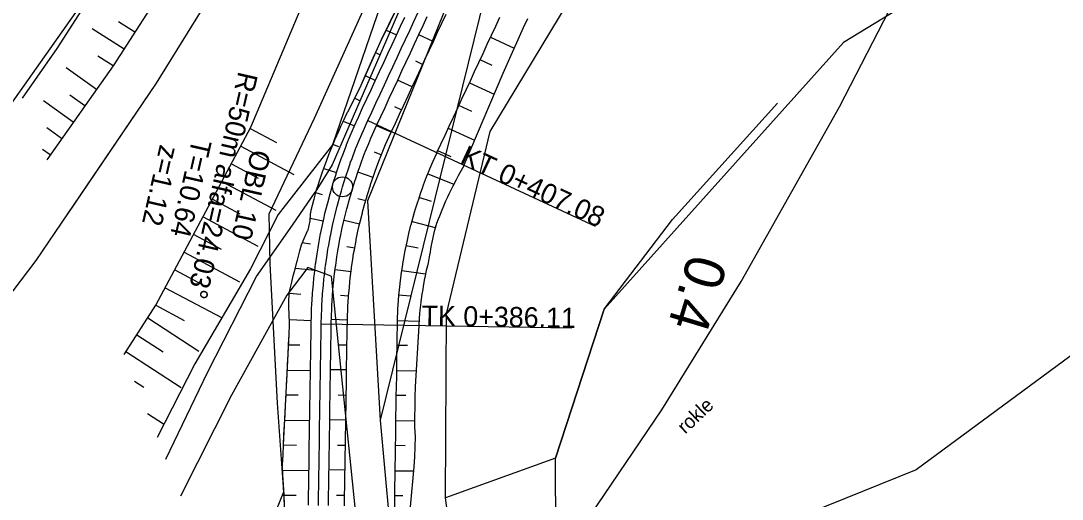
# Model space of a CAD drawing. Extents: x -583721 to -583071, y -1166145 to -1165065.
# Drawn here: x -583498.8 to -583394.9, y -1165295.2 to -1165247.5 of the extents above; entities that cross this region are included whole.
import ezdxf

# ---------------------------------------------------------------- set-up
doc = ezdxf.new("R2010")
doc.units = 0
for name, color, linetype in [('01_DOPRAVA', 7, 'Continuous'), ('03_PC_POPIS_NAVRH', 7, 'Continuous'), ('14', 7, 'Continuous'), ('21', 7, 'Continuous'), ('28', 7, 'Continuous'), ('_Rozpiska', 7, 'Continuous'), ('Kabel_navrh', 7, 'Continuous'), ('KOTY', 7, 'Continuous'), ('Popis PP', 7, 'Continuous'), ('Rámy', 7, 'Continuous'), ('TISK', 7, 'Continuous'), ('Trojúhelniky', 7, 'Continuous')]:
    doc.layers.add(name, color=color, linetype=linetype)

msp = doc.modelspace()

# ---------------------------------------------------------------- linework, layer by layer
at = {"layer": '01_DOPRAVA'}
for points in [[(-583322.15, -1165168.47), (-583340.5, -1165179.46), (-583360.81, -1165200.75), (-583377.25, -1165221.89), (-583390.68, -1165233.74), (-583416.76, -1165249.61), (-583440.61, -1165276.22), (-583445.47, -1165291.1), (-583456.44, -1165295.04)], [(-583479.19, -1165311.26), (-583476.42, -1165303.92), (-583472.55, -1165294.46), (-583473.2, -1165285.59), (-583473.93, -1165271.71), (-583474.02, -1165266.7), (-583469.49, -1165257.18), (-583464.2, -1165245.36), (-583457.16, -1165229.52), (-583453.53, -1165221.51), (-583450.9, -1165215.7), (-583447.13, -1165205.68)], [(-583456.44, -1165295.04), (-583456.33, -1165276.69), (-583451.99, -1165258.51), (-583437.4, -1165234.32), (-583437.26, -1165214.82), (-583447.13, -1165205.68)], [(-583472.25, -1165207.93), (-583489.98, -1165241.85), (-583516.01, -1165278.67)], [(-583327.43, -1165211.57), (-583337.15, -1165221.16), (-583345.28, -1165232.38), (-583356.63, -1165240.96), (-583373.5, -1165261.36), (-583381.99, -1165269.78), (-583390.9, -1165278.52), (-583409.51, -1165292.26), (-583429.18, -1165300.2), (-583454.83, -1165307.19)], [(-583454.83, -1165307.19), (-583455.42, -1165302.7), (-583456.44, -1165295.04)]]:
    msp.add_lwpolyline(points, dxfattribs=at)
at = {"layer": '03_PC_POPIS_NAVRH'}
for points in [[(-583461.6, -1165204.29), (-583455.65, -1165207.26), (-583450.35, -1165210.72), (-583447.26, -1165215.15), (-583446.51, -1165221.03), (-583447.68, -1165226.67), (-583452.2, -1165235.68), (-583464.21, -1165265.43), (-583462.94, -1165287.3)], [(-583463.26, -1165207.24), (-583457.44, -1165210.02), (-583453.98, -1165212.63), (-583451.69, -1165216.62), (-583450.94, -1165221.07), (-583451.57, -1165225.85), (-583455.47, -1165233.56), (-583467.74, -1165261.81), (-583469.44, -1165264.56)], [(-583484.34, -1165291.2), (-583480.19, -1165282.54), (-583475.3, -1165272.95), (-583471.69, -1165267.86), (-583469.44, -1165264.56)], [(-583467.84, -1165272.94), (-583470.17, -1165272.08), (-583472.25, -1165274.84), (-583477.78, -1165284.8), (-583482.88, -1165294.88)], [(-583467.84, -1165272.94), (-583464.75, -1165303.13)], [(-583462.94, -1165287.3), (-583461.59, -1165302.25)]]:
    msp.add_lwpolyline(points, dxfattribs=at)
at = {"layer": '14'}
for p, q in [((-583462.35, -1165248.38), (-583461.32, -1165248.86)), ((-583457.66, -1165249.53), (-583459.11, -1165248.85)), ((-583451.95, -1165249.09), (-583449.59, -1165250.19)), ((-583462.9, -1165250.89), (-583463.42, -1165250.64)), ((-583459.44, -1165251.46), (-583458.71, -1165251.8)), ((-583451.8, -1165251.92), (-583453, -1165251.36)), ((-583464.44, -1165252.93), (-583463.43, -1165253.4)), ((-583459.77, -1165254.06), (-583461.22, -1165253.39)), ((-583454.05, -1165253.63), (-583451.59, -1165254.77)), ((-583464.99, -1165255.43), (-583465.5, -1165255.19)), ((-583461.54, -1165255.99), (-583460.82, -1165256.33)), ((-583453.83, -1165256.49), (-583455.1, -1165255.9)), ((-583466.63, -1165257.46), (-583465.52, -1165257.94)), ((-583461.86, -1165258.58), (-583463.32, -1165257.92)), ((-583456.16, -1165258.16), (-583453.54, -1165259.38)), ((-583467.07, -1165260.02), (-583467.66, -1165259.79)), ((-583463.57, -1165260.52), (-583462.83, -1165260.82)), ((-583455.86, -1165261.04), (-583457.21, -1165260.43)), ((-583468.59, -1165262.18), (-583467.31, -1165262.6)), ((-583463.67, -1165263.08), (-583465.18, -1165262.56)), ((-583458.21, -1165262.72), (-583455.62, -1165263.76)), ((-583468.7, -1165264.81), (-583469.37, -1165264.63)), ((-583465.17, -1165265.17), (-583464.4, -1165265.39)), ((-583457.84, -1165265.48), (-583459.06, -1165265.07)), ((-583469.93, -1165267.14), (-583468.63, -1165267.42)), ((-583465.01, -1165267.73), (-583466.56, -1165267.37)), ((-583459.78, -1165267.47), (-583457.46, -1165268.09)), ((-583469.91, -1165269.74), (-583470.72, -1165269.6)), ((-583466.28, -1165269.96), (-583465.49, -1165270.1)), ((-583459.16, -1165270.15), (-583460.36, -1165269.9)), ((-583471.41, -1165272.12), (-583469.47, -1165272.35)), ((-583465.86, -1165272.49), (-583467.45, -1165272.29)), ((-583460.8, -1165272.36), (-583458.43, -1165272.7)), ((-583470.86, -1165274.76), (-583472.02, -1165274.67)), ((-583466.9, -1165274.83), (-583466.1, -1165274.89)), ((-583459.96, -1165274.94), (-583461.08, -1165274.84)), ((-583472.01, -1165277.27), (-583469.83, -1165277.34)), ((-583466.22, -1165277.32), (-583467.82, -1165277.27)), ((-583461.22, -1165277.34), (-583459.08, -1165277.42)), ((-583470.98, -1165279.82), (-583472.09, -1165279.8)), ((-583467.07, -1165279.78), (-583466.27, -1165279.79)), ((-583460.24, -1165279.85), (-583461.27, -1165279.84)), ((-583472.22, -1165282.3), (-583469.91, -1165282.34)), ((-583466.31, -1165282.29), (-583467.9, -1165282.27)), ((-583461.31, -1165282.34), (-583459.36, -1165282.37)), ((-583471.14, -1165284.82), (-583472.34, -1165284.8)), ((-583467.14, -1165284.78), (-583466.34, -1165284.79)), ((-583460.41, -1165284.85), (-583461.34, -1165284.84)), ((-583472.47, -1165287.3), (-583469.98, -1165287.34)), ((-583466.38, -1165287.29), (-583467.98, -1165287.27)), ((-583461.38, -1165287.34), (-583459.52, -1165287.37)), ((-583471.31, -1165289.81), (-583472.6, -1165289.8)), ((-583467.22, -1165289.78), (-583466.42, -1165289.79)), ((-583460.46, -1165289.85), (-583461.42, -1165289.84)), ((-583472.67, -1165292.29), (-583470.06, -1165292.33)), ((-583466.46, -1165292.29), (-583468.06, -1165292.27)), ((-583461.46, -1165292.34), (-583459.65, -1165292.36)), ((-583471.32, -1165294.82), (-583472.54, -1165294.8)), ((-583467.3, -1165294.78), (-583466.5, -1165294.79)), ((-583460.69, -1165294.85), (-583461.5, -1165294.84))]:
    msp.add_line(p, q, dxfattribs=at)
at = {"layer": '21'}
for points in [[(-583472.33, -1165298.76), (-583472.65, -1165292.75), (-583472.69, -1165291.75), (-583472.64, -1165290.75), (-583472.6, -1165289.75), (-583472.04, -1165278.76), (-583471.99, -1165277.76), (-583471.99, -1165277.65), (-583472.04, -1165276.7), (-583472.06, -1165276.06), (-583472.06, -1165275.64), (-583472.02, -1165274.57), (-583471.99, -1165274.46), (-583471.77, -1165273.52), (-583471.62, -1165272.9), (-583471.51, -1165272.48), (-583471.22, -1165271.45), (-583471.19, -1165271.35), (-583470.98, -1165270.42), (-583470.81, -1165269.81), (-583470.63, -1165269.41), (-583470.19, -1165268.42), (-583470.15, -1165268.33), (-583469.93, -1165267.41), (-583469.92, -1165266.78), (-583469.83, -1165266.36), (-583469.57, -1165265.34), (-583469.55, -1165265.25), (-583469.29, -1165264.33), (-583469.11, -1165263.75), (-583468.98, -1165263.33), (-583468.65, -1165262.34), (-583468.62, -1165262.26), (-583468.29, -1165261.36), (-583468.07, -1165260.79), (-583467.91, -1165260.38), (-583467.51, -1165259.42), (-583467.47, -1165259.34), (-583467.09, -1165258.46), (-583466.84, -1165257.91), (-583466.66, -1165257.51), (-583466.2, -1165256.57), (-583466.16, -1165256.5), (-583465.29, -1165254.78), (-583464.86, -1165253.88), (-583463.23, -1165250.22), (-583462.81, -1165249.32), (-583458.45, -1165240.32)], [(-583472.49, -1165295.76), (-583472.54, -1165294.76), (-583472.6, -1165293.76), (-583472.65, -1165292.75), (-583472.69, -1165291.75), (-583472.64, -1165290.75), (-583472.6, -1165289.75), (-583472.55, -1165288.76), (-583472.5, -1165287.76), (-583472.44, -1165286.76), (-583472.39, -1165285.76), (-583472.34, -1165284.76), (-583472.29, -1165283.76), (-583472.24, -1165282.76), (-583472.19, -1165281.76), (-583472.14, -1165280.76), (-583472.09, -1165279.76), (-583472.04, -1165278.76), (-583471.99, -1165277.76), (-583471.99, -1165277.65), (-583472.04, -1165276.7), (-583472.06, -1165276.06), (-583472.06, -1165275.64), (-583472.02, -1165274.57), (-583471.99, -1165274.46), (-583471.77, -1165273.52), (-583471.62, -1165272.9), (-583471.51, -1165272.48), (-583471.22, -1165271.45), (-583471.19, -1165271.35), (-583470.98, -1165270.42), (-583470.81, -1165269.81), (-583470.63, -1165269.41), (-583470.19, -1165268.42), (-583470.15, -1165268.33), (-583469.93, -1165267.41), (-583469.92, -1165266.78), (-583469.83, -1165266.36), (-583469.57, -1165265.34), (-583469.55, -1165265.25), (-583469.29, -1165264.33), (-583469.11, -1165263.75), (-583468.98, -1165263.33), (-583468.65, -1165262.34), (-583468.62, -1165262.26), (-583468.29, -1165261.36), (-583468.07, -1165260.79), (-583467.91, -1165260.38), (-583467.51, -1165259.42), (-583467.47, -1165259.34), (-583467.09, -1165258.46), (-583466.84, -1165257.91), (-583466.66, -1165257.51), (-583466.2, -1165256.57), (-583466.16, -1165256.5), (-583465.74, -1165255.67), (-583465.29, -1165254.78), (-583464.86, -1165253.88), (-583464.45, -1165252.96), (-583464.05, -1165252.05), (-583463.64, -1165251.14), (-583463.23, -1165250.22), (-583462.81, -1165249.32), (-583462.37, -1165248.42), (-583461.93, -1165247.52), (-583461.5, -1165246.62)], [(-583470.11, -1165295.79), (-583470.1, -1165294.79), (-583470.08, -1165293.79), (-583470.07, -1165292.79), (-583470.05, -1165291.79), (-583470.04, -1165290.79), (-583470.02, -1165289.79), (-583470.01, -1165288.79), (-583469.99, -1165287.79), (-583469.97, -1165286.8), (-583469.96, -1165285.8), (-583469.94, -1165284.8), (-583469.93, -1165283.8), (-583469.91, -1165282.8), (-583469.9, -1165281.8), (-583469.88, -1165280.8), (-583469.87, -1165279.8), (-583469.85, -1165278.8), (-583469.84, -1165277.8), (-583469.83, -1165277.69), (-583469.81, -1165276.78), (-583469.79, -1165276.16), (-583469.77, -1165275.76), (-583469.7, -1165274.74), (-583469.7, -1165274.64), (-583469.62, -1165273.73), (-583469.56, -1165273.11), (-583469.51, -1165272.71), (-583469.39, -1165271.7), (-583469.37, -1165271.6), (-583469.24, -1165270.69), (-583469.15, -1165270.09), (-583469.08, -1165269.68), (-583468.89, -1165268.68), (-583468.87, -1165268.58), (-583468.69, -1165267.68), (-583468.55, -1165267.09), (-583468.46, -1165266.69), (-583468.21, -1165265.7), (-583468.19, -1165265.61), (-583467.95, -1165264.71), (-583467.78, -1165264.13), (-583467.66, -1165263.73), (-583467.36, -1165262.76), (-583467.33, -1165262.68), (-583467.03, -1165261.79), (-583466.84, -1165261.23), (-583466.69, -1165260.83), (-583466.33, -1165259.88), (-583466.3, -1165259.8), (-583465.95, -1165258.93), (-583465.72, -1165258.39), (-583465.55, -1165257.99), (-583465.13, -1165257.06), (-583465.1, -1165256.99), (-583464.71, -1165256.15), (-583464.29, -1165255.25), (-583463.86, -1165254.34), (-583463.44, -1165253.43), (-583463.02, -1165252.53), (-583462.6, -1165251.62), (-583462.18, -1165250.71), (-583461.76, -1165249.81), (-583461.34, -1165248.9), (-583460.92, -1165247.99), (-583460.49, -1165247.09)], [(-583468.11, -1165295.82), (-583468.1, -1165294.82), (-583468.08, -1165293.83), (-583468.07, -1165292.83), (-583468.05, -1165291.83), (-583468.04, -1165290.83), (-583468.02, -1165289.83), (-583468.01, -1165288.83), (-583467.99, -1165287.83), (-583467.98, -1165286.83), (-583467.96, -1165285.83), (-583467.94, -1165284.83), (-583467.93, -1165283.83), (-583467.91, -1165282.83), (-583467.9, -1165281.83), (-583467.88, -1165280.83), (-583467.87, -1165279.83), (-583467.85, -1165278.83), (-583467.84, -1165277.83), (-583467.83, -1165277.72), (-583467.81, -1165276.85), (-583467.79, -1165276.25), (-583467.77, -1165275.87), (-583467.71, -1165274.89), (-583467.7, -1165274.79), (-583467.63, -1165273.91), (-583467.57, -1165273.33), (-583467.53, -1165272.94), (-583467.41, -1165271.96), (-583467.39, -1165271.87), (-583467.27, -1165270.99), (-583467.17, -1165270.42), (-583467.11, -1165270.03), (-583466.93, -1165269.06), (-583466.91, -1165268.97), (-583466.73, -1165268.1), (-583466.6, -1165267.54), (-583466.51, -1165267.15), (-583466.28, -1165266.2), (-583466.26, -1165266.11), (-583466.02, -1165265.25), (-583465.86, -1165264.7), (-583465.75, -1165264.31), (-583465.46, -1165263.37), (-583465.43, -1165263.29), (-583465.14, -1165262.45), (-583464.95, -1165261.91), (-583464.81, -1165261.52), (-583464.47, -1165260.61), (-583464.44, -1165260.53), (-583464.1, -1165259.7), (-583463.88, -1165259.17), (-583463.72, -1165258.8), (-583463.31, -1165257.9), (-583463.28, -1165257.83), (-583462.89, -1165257), (-583462.47, -1165256.09), (-583462.05, -1165255.18), (-583461.63, -1165254.28), (-583461.21, -1165253.37), (-583460.79, -1165252.46), (-583460.37, -1165251.56), (-583459.94, -1165250.65), (-583459.52, -1165249.74), (-583459.1, -1165248.83), (-583458.68, -1165247.93), (-583458.26, -1165247.02)], [(-583466.51, -1165295.85), (-583466.5, -1165294.85), (-583466.48, -1165293.85), (-583466.47, -1165292.85), (-583466.45, -1165291.85), (-583466.44, -1165290.85), (-583466.42, -1165289.85), (-583466.41, -1165288.85), (-583466.39, -1165287.85), (-583466.38, -1165286.85), (-583466.36, -1165285.85), (-583466.34, -1165284.85), (-583466.33, -1165283.85), (-583466.31, -1165282.85), (-583466.3, -1165281.85), (-583466.28, -1165280.85), (-583466.27, -1165279.85), (-583466.25, -1165278.85), (-583466.24, -1165277.85), (-583466.23, -1165277.74), (-583466.21, -1165276.9), (-583466.19, -1165276.32), (-583466.17, -1165275.95), (-583466.11, -1165275.01), (-583466.11, -1165274.91), (-583466.03, -1165274.06), (-583465.98, -1165273.49), (-583465.94, -1165273.12), (-583465.82, -1165272.18), (-583465.81, -1165272.08), (-583465.68, -1165271.24), (-583465.6, -1165270.68), (-583465.53, -1165270.3), (-583465.36, -1165269.37), (-583465.34, -1165269.28), (-583465.17, -1165268.44), (-583465.04, -1165267.89), (-583464.96, -1165267.52), (-583464.73, -1165266.6), (-583464.71, -1165266.52), (-583464.48, -1165265.68), (-583464.33, -1165265.15), (-583464.22, -1165264.77), (-583463.93, -1165263.87), (-583463.91, -1165263.79), (-583463.63, -1165262.97), (-583463.45, -1165262.45), (-583463.31, -1165262.08), (-583462.98, -1165261.19), (-583462.95, -1165261.12), (-583462.62, -1165260.31), (-583462.41, -1165259.81), (-583462.25, -1165259.44), (-583461.86, -1165258.57), (-583461.83, -1165258.51), (-583461.44, -1165257.67), (-583461.02, -1165256.76), (-583460.6, -1165255.86), (-583460.18, -1165254.95), (-583459.76, -1165254.04), (-583459.34, -1165253.14), (-583458.91, -1165252.23), (-583458.49, -1165251.32), (-583458.07, -1165250.42), (-583457.65, -1165249.51), (-583457.23, -1165248.6), (-583456.81, -1165247.69), (-583456.39, -1165246.79)], [(-583461.51, -1165295.93), (-583461.5, -1165294.93), (-583461.48, -1165293.93), (-583461.47, -1165292.93), (-583461.45, -1165291.93), (-583461.44, -1165290.93), (-583461.42, -1165289.93), (-583461.41, -1165288.93), (-583461.39, -1165287.93), (-583461.38, -1165286.93), (-583461.36, -1165285.93), (-583461.35, -1165284.93), (-583461.33, -1165283.93), (-583461.31, -1165282.93), (-583461.3, -1165281.93), (-583461.28, -1165280.93), (-583461.27, -1165279.93), (-583461.25, -1165278.93), (-583461.24, -1165277.93), (-583461.24, -1165277.82), (-583461.22, -1165277.06), (-583461.2, -1165276.55), (-583461.18, -1165276.22), (-583461.13, -1165275.37), (-583461.12, -1165275.28), (-583461.06, -1165274.53), (-583461.01, -1165274.02), (-583460.97, -1165273.68), (-583460.86, -1165272.84), (-583460.85, -1165272.76), (-583460.74, -1165272), (-583460.66, -1165271.5), (-583460.61, -1165271.16), (-583460.45, -1165270.33), (-583460.44, -1165270.25), (-583460.28, -1165269.5), (-583460.17, -1165269.01), (-583460.09, -1165268.67), (-583459.89, -1165267.85), (-583459.87, -1165267.78), (-583459.67, -1165267.03), (-583459.53, -1165266.55), (-583459.43, -1165266.22), (-583459.18, -1165265.41), (-583459.15, -1165265.34), (-583458.91, -1165264.6), (-583458.74, -1165264.14), (-583458.62, -1165263.81), (-583458.32, -1165263.01), (-583458.3, -1165262.95), (-583458, -1165262.23), (-583457.81, -1165261.77), (-583457.67, -1165261.45), (-583457.32, -1165260.67), (-583457.3, -1165260.61), (-583456.91, -1165259.78), (-583456.49, -1165258.87), (-583456.06, -1165257.96), (-583455.64, -1165257.06), (-583455.22, -1165256.15), (-583454.8, -1165255.24), (-583454.38, -1165254.34), (-583453.96, -1165253.43), (-583453.54, -1165252.52), (-583453.12, -1165251.61), (-583452.69, -1165250.71), (-583452.27, -1165249.8), (-583451.85, -1165248.89), (-583451.43, -1165247.99), (-583451.01, -1165247.08)], [(-583448.26, -1165247.26), (-583448.69, -1165248.16), (-583450.32, -1165251.81), (-583450.72, -1165252.73), (-583454.6, -1165261.87), (-583454.62, -1165261.92), (-583455.01, -1165262.62), (-583455.17, -1165262.91), (-583455.39, -1165263.31), (-583455.72, -1165263.96), (-583455.75, -1165264.02), (-583456.1, -1165264.74), (-583456.24, -1165265.04), (-583456.43, -1165265.46), (-583456.72, -1165266.13), (-583456.75, -1165266.19), (-583457.05, -1165266.94), (-583457.17, -1165267.24), (-583457.34, -1165267.69), (-583457.55, -1165268.38), (-583457.56, -1165268.45), (-583457.74, -1165269.23), (-583457.8, -1165269.55), (-583457.89, -1165270.02), (-583458.02, -1165270.73), (-583458.03, -1165270.8), (-583458.18, -1165271.59), (-583458.25, -1165271.9), (-583458.36, -1165272.37), (-583458.5, -1165273.08), (-583458.52, -1165273.16), (-583458.66, -1165273.94), (-583458.71, -1165274.26), (-583458.79, -1165274.74), (-583458.89, -1165275.45), (-583458.9, -1165275.53), (-583458.99, -1165276.33), (-583459.02, -1165276.65), (-583459.06, -1165277.14), (-583459.11, -1165277.85), (-583459.45, -1165283.96), (-583459.49, -1165284.96), (-583459.52, -1165287.96), (-583459.48, -1165288.96), (-583459.5, -1165289.96), (-583459.53, -1165290.96), (-583459.61, -1165291.96), (-583459.98, -1165295.95)]]:
    msp.add_lwpolyline(points, dxfattribs=at)
at = {"layer": '_Rozpiska'}
for points in [[(-583487.42, -1165248.59), (-583489.04, -1165247.55)], [(-583488.5, -1165250.28), (-583491.66, -1165248.25)], [(-583489.58, -1165251.96), (-583491.12, -1165250.97)], [(-583491.23, -1165254.31), (-583494.26, -1165252.15)], [(-583493.56, -1165257.56), (-583496.53, -1165255.44)], [(-583492.4, -1165255.93), (-583493.89, -1165254.86)], [(-583494.72, -1165259.19), (-583496.19, -1165258.14)], [(-583475.91, -1165258.19), (-583473.28, -1165259.6)], [(-583476.85, -1165259.96), (-583471.55, -1165262.78)], [(-583495.88, -1165260.82), (-583496.62, -1165260.29)], [(-583477.79, -1165261.72), (-583475.12, -1165263.15)], [(-583478.73, -1165263.49), (-583473.36, -1165266.36)], [(-583479.67, -1165265.25), (-583476.96, -1165266.7)], [(-583480.61, -1165267.02), (-583475.16, -1165269.93)], [(-583481.55, -1165268.78), (-583478.81, -1165270.25)], [(-583482.5, -1165270.55), (-583476.97, -1165273.5)], [(-583483.44, -1165272.31), (-583480.65, -1165273.8)], [(-583484.38, -1165274.08), (-583478.77, -1165277.07)], [(-583485.32, -1165275.84), (-583482.5, -1165277.35)], [(-583486.14, -1165277.1), (-583481.05, -1165280.4)], [(-583487.23, -1165278.78), (-583484.58, -1165280.49)], [(-583488.31, -1165280.45), (-583482.81, -1165284.03)], [(-583487.44, -1165283.4), (-583486.54, -1165283.99)], [(-583486.16, -1165286.62), (-583484.56, -1165287.66)]]:
    msp.add_lwpolyline(points, dxfattribs=at)
at = {"layer": 'Kabel_navrh'}
for points in [[(-583489.59, -1165168.85), (-583487.13, -1165174.9), (-583482.66, -1165187.08), (-583477.45, -1165201.72), (-583475.94, -1165206.86), (-583475.94, -1165214.62), (-583478.55, -1165222.21), (-583487.05, -1165237.5), (-583495.21, -1165250.22), (-583498.66, -1165255.16)], [(-583442.72, -1165208.75), (-583451.97, -1165242.6), (-583458.06, -1165267.49), (-583462.94, -1165287.3)], [(-583409.51, -1165292.26), (-583429.18, -1165300.2), (-583443.59, -1165301.75), (-583445.45, -1165298.71), (-583445.47, -1165291.1), (-583440.61, -1165276.22), (-583433.8, -1165267.29), (-583423.34, -1165255.69)]]:
    msp.add_lwpolyline(points, dxfattribs=at)
at = {"layer": 'KOTY'}
msp.add_lwpolyline([(-583469.11, -1165295.81), (-583469.1, -1165294.81), (-583469.08, -1165293.81), (-583469.07, -1165292.81), (-583469.05, -1165291.81), (-583469.04, -1165290.81), (-583469.02, -1165289.81), (-583469.01, -1165288.81), (-583468.99, -1165287.81), (-583468.98, -1165286.81), (-583468.96, -1165285.81), (-583468.94, -1165284.81), (-583468.93, -1165283.81), (-583468.91, -1165282.81), (-583468.9, -1165281.81), (-583468.88, -1165280.81), (-583468.87, -1165279.81), (-583468.85, -1165278.81), (-583468.84, -1165277.81), (-583468.83, -1165277.7), (-583468.81, -1165276.81), (-583468.79, -1165276.21), (-583468.77, -1165275.81), (-583468.71, -1165274.81), (-583468.7, -1165274.71), (-583468.62, -1165273.82), (-583468.56, -1165273.22), (-583468.52, -1165272.82), (-583468.4, -1165271.83), (-583468.38, -1165271.73), (-583468.25, -1165270.84), (-583468.16, -1165270.25), (-583468.09, -1165269.85), (-583467.91, -1165268.87), (-583467.89, -1165268.78), (-583467.71, -1165267.89), (-583467.58, -1165267.31), (-583467.49, -1165266.92), (-583467.25, -1165265.95), (-583467.22, -1165265.86), (-583466.99, -1165264.98), (-583466.82, -1165264.42), (-583466.71, -1165264.02), (-583466.41, -1165263.07), (-583466.38, -1165262.98), (-583466.09, -1165262.12), (-583465.9, -1165261.57), (-583465.75, -1165261.18), (-583465.4, -1165260.24), (-583465.37, -1165260.17), (-583465.02, -1165259.31), (-583464.8, -1165258.78), (-583464.63, -1165258.39), (-583464.22, -1165257.48), (-583464.19, -1165257.41), (-583463.8, -1165256.58), (-583463.38, -1165255.67), (-583462.96, -1165254.76), (-583462.54, -1165253.86), (-583462.11, -1165252.95), (-583461.69, -1165252.04), (-583461.27, -1165251.13), (-583460.85, -1165250.23), (-583460.43, -1165249.32), (-583460.01, -1165248.41), (-583459.59, -1165247.51), (-583459.17, -1165246.6)], dxfattribs=at)
at = {"layer": 'Popis PP'}
for points in [[(-583699.75, -1165419.22), (-583679.21, -1165411.61), (-583666.5, -1165406.36), (-583648.68, -1165398.32), (-583628.68, -1165388.05), (-583609.64, -1165376.84), (-583593.26, -1165365.98), (-583583.56, -1165359), (-583567.75, -1165346.63), (-583555.85, -1165336.47), (-583546.78, -1165328.15), (-583532.96, -1165314.38), (-583520.45, -1165300.56), (-583509.78, -1165287.87), (-583497.25, -1165271.38), (-583485.27, -1165253.68), (-583478.66, -1165242.98), (-583469.98, -1165227.56), (-583463.28, -1165214.57)], [(-583494.08, -1165266.69), (-583485.27, -1165253.68), (-583478.66, -1165242.98), (-583469.98, -1165227.56), (-583463.28, -1165214.57)], [(-583678.9, -1165475.48), (-583657.33, -1165467.49), (-583642.7, -1165461.45), (-583622.62, -1165452.39), (-583599.73, -1165440.63), (-583577.82, -1165427.73), (-583559.15, -1165415.35), (-583547.54, -1165407), (-583529.77, -1165393.09), (-583516.08, -1165381.41), (-583505.31, -1165371.53), (-583489.52, -1165355.79), (-583475.23, -1165340.01), (-583462.9, -1165325.35), (-583448.48, -1165306.37), (-583434.88, -1165286.28), (-583426.97, -1165273.48), (-583417.16, -1165256.04), (-583409.96, -1165242.07)]]:
    msp.add_lwpolyline(points, dxfattribs=at)
at = {"layer": 'Rámy'}
for points in [[(-583488.5, -1165280.74), (-583485.32, -1165275.84), (-583475.84, -1165258.07), (-583466.53, -1165235.95), (-583459.06, -1165218.81), (-583458.18, -1165215.1), (-583458.58, -1165212.7)], [(-583455.18, -1165215.77), (-583453.16, -1165222.7), (-583461.44, -1165241.5), (-583467.71, -1165259.84), (-583473.13, -1165266.78)], [(-583471.39, -1165219.76), (-583481.02, -1165238.62), (-583489.58, -1165251.96), (-583496.21, -1165261.33)], [(-583473.13, -1165266.78), (-583475.9, -1165272.19), (-583481.43, -1165281.67), (-583485.2, -1165289.04)]]:
    msp.add_lwpolyline(points, dxfattribs=at)
at = {"layer": 'TISK'}
for points in [[(-583464.19, -1165257.41), (-583441.51, -1165267.94)], [(-583468.83, -1165277.7), (-583443.84, -1165278.09)]]:
    msp.add_lwpolyline(points, dxfattribs=at)
at = {"layer": 'Trojúhelniky'}
msp.add_circle((-583466.71, -1165264.02), 1, dxfattribs=at)

# ---------------------------------------------------------------- texts
at = {"layer": '28'}
msp.add_text('rokle', height=1.4, rotation=43.4875, dxfattribs=at).set_placement((-583432.53, -1165288.74))
at = {"layer": 'TISK'}
for s, height, rotation, p in [('R=50m alfa=24.03%%d', 2, 257.1024, (-583477.08, -1165252.43)), ('   z=1.12', 2, 257.1024, (-583484.41, -1165257.56)), ('  T=10.64', 2, 257.1024, (-583481.36, -1165257.69)), ('KT 0+407.08', 2, 335.0882, (-583455.12, -1165261.63)), ('OBL 10', 2, 257.1024, (-583475.78, -1165260.2)), ('0.4', 4, 253.1975, (-583432.12, -1165270.55)), ('TK 0+386.11', 2, 359.1166, (-583458.84, -1165277.86))]:
    msp.add_text(s, height=height, rotation=rotation, dxfattribs=at).set_placement(p)

doc.saveas('drawing.dxf')
